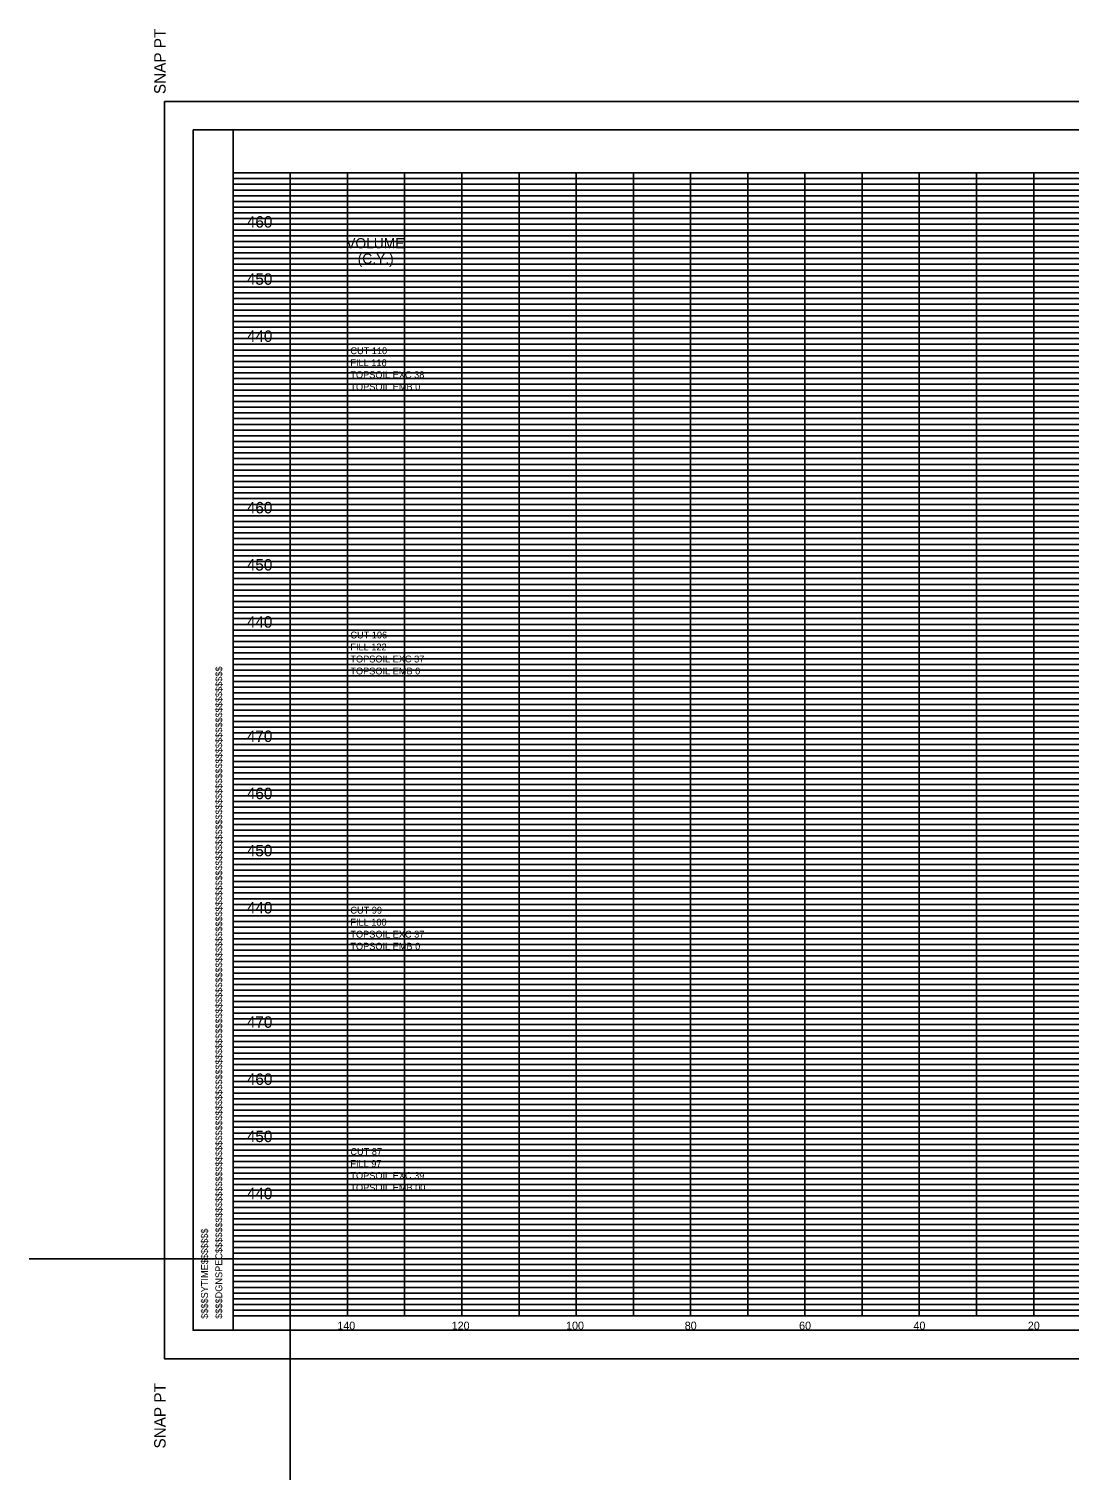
# Model space of a CAD drawing. Extents: x 37 to 1710, y 707 to 2305.
# Drawn here: x 964.3 to 1146.3, y 1511.3 to 1765.2 of the extents above; entities that cross this region are included whole.
import ezdxf

# ---------------------------------------------------------------- set-up
doc = ezdxf.new("R2010")
doc.units = 0
for name, color, linetype in [('DESIGN - SCRATCH - User 1', 7, 'Continuous'), ('DESIGN - SHEET - Corner Text', 7, 'Continuous'), ('DESIGN - SHEET - Light Grid', 7, 'Continuous'), ('DESIGN - SHEET - Linework', 7, 'Continuous'), ('DESIGN - SHEET - Plot Shape', 7, 'Continuous'), ('DESIGN - TYPICAL - Text', 7, 'Continuous')]:
    doc.layers.add(name, color=color, linetype=linetype)

msp = doc.modelspace()

# ---------------------------------------------------------------- linework, layer by layer
at = {"layer": 'DESIGN - SCRATCH - User 1'}
for p, q in [((1010, 1550), (964.31, 1550)), ((1010, 1550), (1010, 1511.3)), ((1000, 1540), (1000, 1540))]:
    msp.add_line(p, q, dxfattribs=at)
at = {"layer": 'DESIGN - SHEET - Light Grid'}
for p, q in [((1000, 1739), (1280, 1739)), ((1000, 1738), (1280, 1738)), ((1000, 1737), (1320, 1737)), ((1000, 1736), (1320, 1736)), ((1000, 1735), (1320, 1735)), ((1000, 1734), (1320, 1734)), ((1000, 1733), (1320, 1733)), ((1000, 1732), (1320, 1732)), ((1000, 1731), (1320, 1731)), ((1000, 1729), (1320, 1729)), ((1000, 1728), (1320, 1728)), ((1000, 1727), (1320, 1727)), ((1000, 1726), (1320, 1726)), ((1000, 1725), (1320, 1725)), ((1000, 1724), (1320, 1724)), ((1000, 1723), (1320, 1723)), ((1000, 1722), (1320, 1722)), ((1000, 1721), (1320, 1721)), ((1000, 1719), (1320, 1719)), ((1000, 1718), (1320, 1718)), ((1000, 1717), (1320, 1717)), ((1000, 1716), (1320, 1716)), ((1000, 1715), (1320, 1715)), ((1000, 1714), (1320, 1714)), ((1000, 1713), (1320, 1713)), ((1000, 1712), (1320, 1712)), ((1000, 1711), (1320, 1711)), ((1000, 1709), (1320, 1709)), ((1000, 1708), (1320, 1708)), ((1000, 1707), (1320, 1707)), ((1000, 1706), (1320, 1706)), ((1000, 1705), (1320, 1705)), ((1000, 1704), (1320, 1704)), ((1000, 1703), (1320, 1703)), ((1000, 1702), (1320, 1702)), ((1000, 1701), (1320, 1701)), ((1000, 1699), (1320, 1699)), ((1000, 1698), (1320, 1698)), ((1000, 1697), (1320, 1697)), ((1000, 1696), (1320, 1696)), ((1000, 1695), (1320, 1695)), ((1000, 1694), (1320, 1694)), ((1000, 1693), (1320, 1693)), ((1000, 1692), (1320, 1692)), ((1000, 1691), (1320, 1691)), ((1000, 1689), (1320, 1689)), ((1000, 1688), (1320, 1688)), ((1000, 1687), (1320, 1687)), ((1000, 1686), (1320, 1686)), ((1000, 1685), (1320, 1685)), ((1000, 1684), (1320, 1684)), ((1000, 1683), (1320, 1683)), ((1000, 1682), (1320, 1682)), ((1000, 1681), (1320, 1681)), ((1000, 1679), (1320, 1679)), ((1000, 1678), (1320, 1678)), ((1000, 1677), (1320, 1677)), ((1000, 1676), (1320, 1676)), ((1000, 1675), (1320, 1675)), ((1000, 1674), (1320, 1674)), ((1000, 1673), (1320, 1673)), ((1000, 1672), (1320, 1672)), ((1000, 1671), (1320, 1671)), ((1000, 1669), (1320, 1669)), ((1000, 1668), (1320, 1668)), ((1000, 1667), (1320, 1667)), ((1000, 1666), (1320, 1666)), ((1000, 1665), (1320, 1665)), ((1000, 1664), (1320, 1664)), ((1000, 1663), (1320, 1663)), ((1000, 1662), (1320, 1662)), ((1000, 1661), (1320, 1661)), ((1000, 1659), (1320, 1659)), ((1000, 1658), (1320, 1658)), ((1000, 1657), (1320, 1657)), ((1000, 1656), (1320, 1656)), ((1000, 1655), (1320, 1655)), ((1000, 1654), (1320, 1654)), ((1000, 1653), (1320, 1653)), ((1000, 1652), (1320, 1652)), ((1000, 1651), (1320, 1651)), ((1000, 1649), (1320, 1649)), ((1000, 1648), (1320, 1648)), ((1000, 1647), (1320, 1647)), ((1000, 1646), (1320, 1646)), ((1000, 1645), (1320, 1645)), ((1000, 1644), (1320, 1644)), ((1000, 1643), (1320, 1643)), ((1000, 1642), (1320, 1642)), ((1000, 1641), (1320, 1641)), ((1000, 1639), (1320, 1639)), ((1000, 1638), (1320, 1638)), ((1000, 1637), (1320, 1637)), ((1000, 1636), (1320, 1636)), ((1000, 1635), (1320, 1635)), ((1000, 1634), (1320, 1634)), ((1000, 1633), (1320, 1633)), ((1000, 1632), (1320, 1632)), ((1000, 1631), (1320, 1631)), ((1000, 1629), (1320, 1629)), ((1000, 1628), (1320, 1628)), ((1000, 1627), (1320, 1627)), ((1000, 1626), (1320, 1626)), ((1000, 1625), (1320, 1625)), ((1000, 1624), (1320, 1624)), ((1000, 1623), (1320, 1623)), ((1000, 1622), (1320, 1622)), ((1000, 1621), (1320, 1621)), ((1000, 1619), (1320, 1619)), ((1000, 1618), (1320, 1618)), ((1000, 1617), (1320, 1617)), ((1000, 1616), (1320, 1616)), ((1000, 1615), (1320, 1615)), ((1000, 1614), (1320, 1614)), ((1000, 1613), (1320, 1613)), ((1000, 1612), (1320, 1612)), ((1000, 1611), (1320, 1611)), ((1000, 1609), (1320, 1609)), ((1000, 1608), (1320, 1608)), ((1000, 1607), (1320, 1607)), ((1000, 1606), (1320, 1606)), ((1000, 1605), (1320, 1605)), ((1000, 1604), (1320, 1604)), ((1000, 1603), (1320, 1603)), ((1000, 1602), (1320, 1602)), ((1000, 1601), (1320, 1601)), ((1000, 1599), (1320, 1599)), ((1000, 1598), (1320, 1598)), ((1000, 1597), (1320, 1597)), ((1000, 1596), (1320, 1596)), ((1000, 1595), (1320, 1595)), ((1000, 1594), (1320, 1594)), ((1000, 1593), (1320, 1593)), ((1000, 1592), (1320, 1592)), ((1000, 1591), (1320, 1591)), ((1000, 1589), (1320, 1589)), ((1000, 1588), (1320, 1588)), ((1000, 1587), (1320, 1587)), ((1000, 1586), (1320, 1586)), ((1000, 1585), (1320, 1585)), ((1000, 1584), (1320, 1584)), ((1000, 1583), (1320, 1583)), ((1000, 1582), (1320, 1582)), ((1000, 1581), (1320, 1581)), ((1000, 1579), (1320, 1579)), ((1000, 1578), (1320, 1578)), ((1000, 1577), (1320, 1577)), ((1000, 1576), (1320, 1576)), ((1000, 1575), (1320, 1575)), ((1000, 1574), (1320, 1574)), ((1000, 1573), (1320, 1573)), ((1000, 1572), (1320, 1572)), ((1000, 1571), (1320, 1571)), ((1000, 1569), (1320, 1569)), ((1000, 1568), (1320, 1568)), ((1000, 1567), (1320, 1567)), ((1000, 1566), (1320, 1566)), ((1000, 1565), (1320, 1565)), ((1000, 1564), (1320, 1564)), ((1000, 1563), (1320, 1563)), ((1000, 1562), (1320, 1562)), ((1000, 1561), (1320, 1561)), ((1000, 1559), (1320, 1559)), ((1000, 1558), (1320, 1558)), ((1000, 1557), (1320, 1557)), ((1000, 1556), (1320, 1556)), ((1000, 1555), (1320, 1555)), ((1000, 1554), (1320, 1554)), ((1000, 1553), (1320, 1553)), ((1000, 1552), (1320, 1552)), ((1000, 1551), (1320, 1551)), ((1000, 1549), (1320, 1549)), ((1000, 1548), (1320, 1548)), ((1000, 1547), (1320, 1547)), ((1000, 1546), (1320, 1546)), ((1000, 1545), (1320, 1545)), ((1000, 1544), (1320, 1544)), ((1000, 1543), (1320, 1543)), ((1000, 1542), (1320, 1542)), ((1000, 1541), (1320, 1541))]:
    msp.add_line(p, q, dxfattribs=at)
at = {"layer": 'DESIGN - SHEET - Linework'}
for p, q in [((1000, 1740), (1320, 1740)), ((1010, 1540), (1010, 1740)), ((1020, 1540), (1020, 1740)), ((1030, 1540), (1030, 1740)), ((1040, 1540), (1040, 1740)), ((1050, 1540), (1050, 1740)), ((1060, 1540), (1060, 1740)), ((1070, 1540), (1070, 1740)), ((1080, 1540), (1080, 1740)), ((1090, 1540), (1090, 1740)), ((1100, 1540), (1100, 1740)), ((1110, 1540), (1110, 1740)), ((1120, 1540), (1120, 1740)), ((1130, 1540), (1130, 1740)), ((1140, 1540), (1140, 1740)), ((1000, 1730), (1320, 1730)), ((1000, 1720), (1320, 1720)), ((1000, 1710), (1320, 1710)), ((1000, 1700), (1320, 1700)), ((1000, 1690), (1320, 1690)), ((1000, 1680), (1320, 1680)), ((1000, 1670), (1320, 1670)), ((1000, 1660), (1320, 1660)), ((1000, 1650), (1320, 1650)), ((1000, 1640), (1320, 1640)), ((1000, 1630), (1320, 1630)), ((1000, 1620), (1320, 1620)), ((1000, 1610), (1320, 1610)), ((1000, 1600), (1320, 1600)), ((1000, 1590), (1320, 1590)), ((1000, 1580), (1320, 1580)), ((1000, 1570), (1320, 1570)), ((1000, 1560), (1320, 1560)), ((1000, 1550), (1320, 1550)), ((1000, 1540), (1320, 1540))]:
    msp.add_line(p, q, dxfattribs=at)
for points in [[(988, 1752.5), (1328, 1752.5), (1328, 1532.5), (988, 1532.5)], [(1000, 1747.5), (1320, 1747.5), (1320, 1537.5), (1000, 1537.5)]]:
    msp.add_lwpolyline(points, close=True, dxfattribs=at)
at = {"layer": 'DESIGN - SHEET - Plot Shape'}
msp.add_lwpolyline([(993, 1747.5), (1323, 1747.5), (1323, 1537.5), (993, 1537.5)], close=True, dxfattribs=at)

# ---------------------------------------------------------------- texts
at = {"layer": 'DESIGN - SHEET - Corner Text'}
for s, height, p in [('  SNAP PT', 2, (988.2, 1752.3)), ('$$$$DGNSPEC$$$$$$$$$$$$$$$$$$$$$$$$$$$$$$$$$$$$$$$$$$$$$$$$$$$$$$$$$$$$$$$$$$$$$$$$$$$$$$$$$$$$$$$$$$$$$$$$$$$$$$$$$$$$$$$$$$$', 1.2, (998.1, 1539.5)), ('$$$$SYTIME$$$$$$$', 1.2, (995.6, 1539.5)), ('SNAP PT  ', 2, (988.2, 1516.8))]:
    msp.add_text(s, height=height, rotation=90, dxfattribs=at).set_placement(p)
at = {"layer": 'DESIGN - TYPICAL - Text'}
for s, height, p in [('     460     ', 2, (998.69, 1730.42)), ('VOLUME', 1.8, (1019.79, 1726.79)), ('   (C.Y.)', 1.8, (1019.79, 1724.09)), ('     450     ', 2, (998.69, 1720.42)), ('     440     ', 2, (998.69, 1710.42)), ('CUT 110', 1.2, (1020.51, 1708.28)), ('FILL 116', 1.2, (1020.51, 1706.18)), ('TOPSOIL EXC 38', 1.2, (1020.51, 1704.08)), ('TOPSOIL EMB 0', 1.2, (1020.51, 1701.98)), ('     460     ', 2, (998.69, 1680.42)), ('     450     ', 2, (998.69, 1670.42)), ('     440     ', 2, (998.69, 1660.42)), ('CUT 106', 1.2, (1020.51, 1658.54)), ('TOPSOIL EXC 37', 1.2, (1020.51, 1654.34)), ('FILL 122', 1.2, (1020.51, 1656.44)), ('TOPSOIL EMB 0', 1.2, (1020.51, 1652.24)), ('     470     ', 2, (998.69, 1640.42)), ('     460     ', 2, (998.69, 1630.42)), ('     450     ', 2, (998.69, 1620.42)), ('     440     ', 2, (998.69, 1610.42)), ('CUT 99', 1.2, (1020.51, 1610.39)), ('TOPSOIL EXC 37', 1.2, (1020.51, 1606.19)), ('FILL 100', 1.2, (1020.51, 1608.29)), ('TOPSOIL EMB 0', 1.2, (1020.51, 1604.09)), ('     470     ', 2, (998.69, 1590.42)), ('     460     ', 2, (998.69, 1580.42)), ('     450     ', 2, (998.69, 1570.42)), ('CUT 87', 1.2, (1020.51, 1568.16)), ('FILL 97', 1.2, (1020.51, 1566.06)), ('TOPSOIL EXC 39', 1.2, (1020.51, 1563.96)), ('     440     ', 2, (998.69, 1560.42)), ('TOPSOIL EMB 00', 1.2, (1020.51, 1561.86)), ('     140     ', 1.4, (1015.63, 1537.6)), ('     120     ', 1.4, (1035.63, 1537.6)), ('     100     ', 1.4, (1055.63, 1537.6)), ('     80     ', 1.4, (1076.38, 1537.6)), ('     60     ', 1.4, (1096.38, 1537.6)), ('     40     ', 1.4, (1116.38, 1537.6)), ('     20     ', 1.4, (1136.38, 1537.6))]:
    msp.add_text(s, height=height, dxfattribs=at).set_placement(p)

doc.saveas('drawing.dxf')
